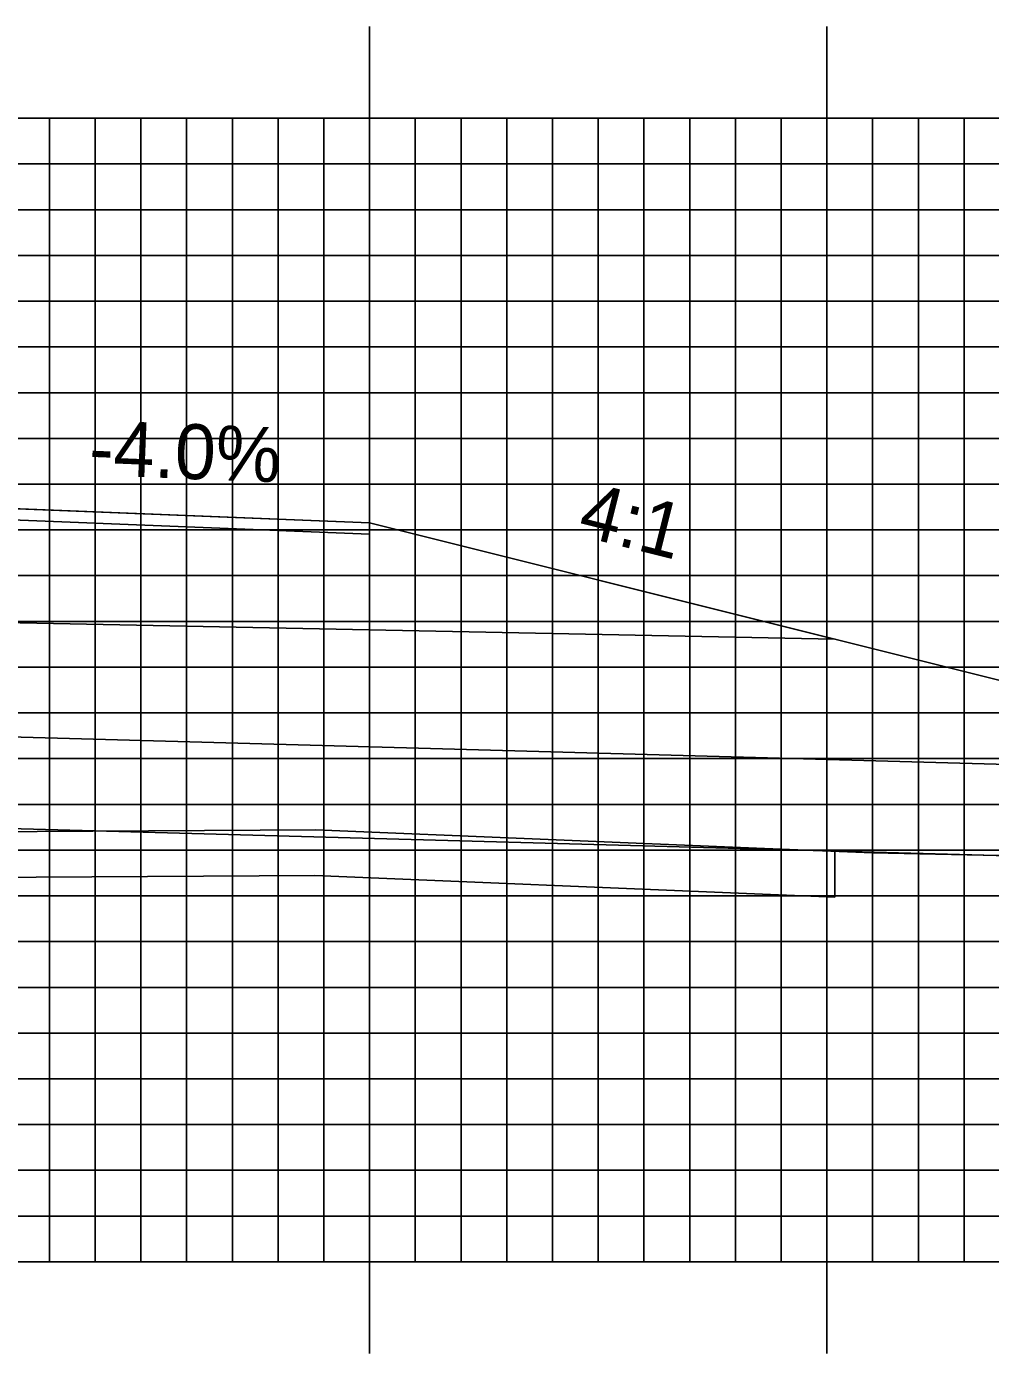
# Model space of a CAD drawing. Extents: x 1771235 to 1771579, y 442591 to 442811.
# Drawn here: x 1771413.57 to 1771434.64, y 442696.66 to 442725.67 of the extents above; entities that cross this region are included whole.
import ezdxf

# ---------------------------------------------------------------- set-up
doc = ezdxf.new("R2010")
doc.units = 0
for name, color, linetype in [('ANNOTATION', 7, 'Continuous'), ('D_Drainage_Culvert', 7, 'Continuous'), ('D_Roadway_Centerline', 7, 'Continuous'), ('D_Roadway_Edge_Shoulder', 7, 'Continuous'), ('D_Roadway_SlopeLines', 7, 'Continuous'), ('D_Roadway_SubGrade', 7, 'Continuous'), ('GRUBBING IN FILL', 7, 'Continuous'), ('MAJOR', 7, 'Continuous'), ('MINOR', 7, 'Continuous'), ('S_Roadway_Centerline', 7, 'Continuous')]:
    doc.layers.add(name, color=color, linetype=linetype)

msp = doc.modelspace()

# ---------------------------------------------------------------- linework, layer by layer
at = {"layer": 'D_Drainage_Culvert'}
for p, q in [((1771365.291, 442711.463), (1771445.349, 442709.255)), ((1771365.236, 442709.463), (1771445.294, 442707.255))]:
    msp.add_line(p, q, dxfattribs=at)
at = {"layer": 'D_Roadway_Centerline'}
msp.add_lwpolyline([(1771370.893, 442712.277), (1771371.045, 442712.315), (1771381.067, 442714.82), (1771388.948, 442715.136), (1771389.067, 442715.14), (1771400.889, 442715.377), (1771401.067, 442715.38), (1771401.246, 442715.377), (1771413.067, 442715.14), (1771413.187, 442715.136), (1771421.067, 442714.82), (1771431.09, 442712.315), (1771431.241, 442712.277), (1771439.262, 442710.272)], dxfattribs=at)
at = {"layer": 'D_Roadway_Edge_Shoulder'}
msp.add_lwpolyline([(1771413.067, 442715.14), (1771421.067, 442714.82), (1771421.067, 442714.57), (1771413.067, 442714.89)], close=True, dxfattribs=at)
at = {"layer": 'D_Roadway_SlopeLines'}
msp.add_lwpolyline([(1771421.067, 442714.82), (1771431.241, 442712.277), (1771439.262, 442710.272)], dxfattribs=at)
at = {"layer": 'D_Roadway_SubGrade'}
msp.add_lwpolyline([(1771389.067, 442712.64), (1771370.893, 442712.277), (1771381.067, 442714.82), (1771381.067, 442714.57), (1771389.067, 442714.89), (1771401.067, 442715.13), (1771413.067, 442714.89), (1771421.067, 442714.57), (1771421.067, 442714.82), (1771431.241, 442712.277), (1771413.067, 442712.64), (1771401.067, 442712.88)], close=True, dxfattribs=at)
at = {"layer": 'GRUBBING IN FILL'}
msp.add_line((1771431.241, 442707.636), (1771431.241, 442706.635), dxfattribs=at)
msp.add_line((1771431.241, 442707.636), (1771431.241, 442706.635), dxfattribs=at)
msp.add_lwpolyline([(1771370.893, 442708.355), (1771372.866, 442708.25), (1771378.513, 442707.825), (1771384.758, 442707.644), (1771388.863, 442707.337), (1771406.939, 442707.097), (1771408.11, 442707.073), (1771408.898, 442707.041), (1771419.874, 442707.107), (1771429.658, 442706.701), (1771431.241, 442706.635)], dxfattribs=at)
msp.add_lwpolyline([(1771370.893, 442708.355), (1771372.866, 442708.25), (1771378.513, 442707.825), (1771384.758, 442707.644), (1771388.863, 442707.337), (1771406.939, 442707.097), (1771408.11, 442707.073), (1771408.898, 442707.041), (1771419.874, 442707.107), (1771429.658, 442706.701), (1771431.241, 442706.635)], dxfattribs=at)
at = {"layer": 'MAJOR'}
for p, q in [((1771421.067, 442725.669), (1771421.067, 442723.665)), ((1771431.067, 442725.669), (1771431.067, 442723.665)), ((1771261.067, 442723.665), (1771541.067, 442723.665)), ((1771261.067, 442723.665), (1771541.067, 442723.665)), ((1771421.067, 442698.665), (1771421.067, 442723.665)), ((1771431.067, 442698.665), (1771431.067, 442723.665)), ((1771261.067, 442718.665), (1771541.067, 442718.665)), ((1771261.067, 442713.665), (1771541.067, 442713.665)), ((1771261.067, 442708.665), (1771541.067, 442708.665)), ((1771261.067, 442703.665), (1771541.067, 442703.665)), ((1771261.067, 442698.665), (1771541.067, 442698.665)), ((1771261.067, 442698.665), (1771541.067, 442698.665)), ((1771421.067, 442696.661), (1771421.067, 442698.665)), ((1771431.067, 442696.661), (1771431.067, 442698.665))]:
    msp.add_line(p, q, dxfattribs=at)
at = {"layer": 'MINOR'}
for p, q in [((1771414.067, 442698.665), (1771414.067, 442723.665)), ((1771415.067, 442698.665), (1771415.067, 442723.665)), ((1771416.067, 442698.665), (1771416.067, 442723.665)), ((1771417.067, 442698.665), (1771417.067, 442723.665)), ((1771418.067, 442698.665), (1771418.067, 442723.665)), ((1771419.067, 442698.665), (1771419.067, 442723.665)), ((1771420.067, 442698.665), (1771420.067, 442723.665)), ((1771422.067, 442698.665), (1771422.067, 442723.665)), ((1771423.067, 442698.665), (1771423.067, 442723.665)), ((1771424.067, 442698.665), (1771424.067, 442723.665)), ((1771425.067, 442698.665), (1771425.067, 442723.665)), ((1771426.067, 442698.665), (1771426.067, 442723.665)), ((1771427.067, 442698.665), (1771427.067, 442723.665)), ((1771428.067, 442698.665), (1771428.067, 442723.665)), ((1771429.067, 442698.665), (1771429.067, 442723.665)), ((1771430.067, 442698.665), (1771430.067, 442723.665)), ((1771432.067, 442698.665), (1771432.067, 442723.665)), ((1771433.067, 442698.665), (1771433.067, 442723.665)), ((1771434.067, 442698.665), (1771434.067, 442723.665)), ((1771261.067, 442722.665), (1771541.067, 442722.665)), ((1771261.067, 442721.665), (1771541.067, 442721.665)), ((1771261.067, 442720.665), (1771541.067, 442720.665)), ((1771261.067, 442719.665), (1771541.067, 442719.665)), ((1771261.067, 442717.665), (1771541.067, 442717.665)), ((1771261.067, 442716.665), (1771541.067, 442716.665)), ((1771261.067, 442715.665), (1771541.067, 442715.665)), ((1771261.067, 442714.665), (1771541.067, 442714.665)), ((1771261.067, 442712.665), (1771541.067, 442712.665)), ((1771261.067, 442711.665), (1771541.067, 442711.665)), ((1771261.067, 442710.665), (1771541.067, 442710.665)), ((1771261.067, 442709.665), (1771541.067, 442709.665)), ((1771261.067, 442707.665), (1771541.067, 442707.665)), ((1771261.067, 442706.665), (1771541.067, 442706.665)), ((1771261.067, 442705.665), (1771541.067, 442705.665)), ((1771261.067, 442704.665), (1771541.067, 442704.665)), ((1771261.067, 442702.665), (1771541.067, 442702.665)), ((1771261.067, 442701.665), (1771541.067, 442701.665)), ((1771261.067, 442700.665), (1771541.067, 442700.665)), ((1771261.067, 442699.665), (1771541.067, 442699.665))]:
    msp.add_line(p, q, dxfattribs=at)
at = {"layer": 'S_Roadway_Centerline'}
msp.add_lwpolyline([(1771328.588, 442710.405), (1771346.503, 442709.868), (1771348.907, 442709.803), (1771349.353, 442709.787), (1771349.877, 442709.796), (1771369.609, 442709.425), (1771372.93, 442709.248), (1771378.565, 442708.824), (1771384.81, 442708.643), (1771388.907, 442708.337), (1771406.956, 442708.096), (1771408.14, 442708.073), (1771408.915, 442708.041), (1771419.892, 442708.107), (1771429.7, 442707.701), (1771432.066, 442707.602), (1771435.861, 442707.523), (1771443.742, 442707.524), (1771448.815, 442707.162), (1771463.73, 442706.723)], dxfattribs=at)

# ---------------------------------------------------------------- texts
at = {"layer": 'ANNOTATION'}
for s, rotation, p in [('-4.0%', 357.7094, (1771414.919, 442715.868)), ('4:1', 345.9638, (1771425.584, 442714.553))]:
    msp.add_text(s, height=1.2, rotation=rotation, dxfattribs=at).set_placement(p)

doc.saveas('drawing.dxf')
